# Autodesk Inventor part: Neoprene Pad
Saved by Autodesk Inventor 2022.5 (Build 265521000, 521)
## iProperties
Created: 2025-02
Part Number: Neoprene Pad
Material: Generic
Document SubType Name: Modeling
Designer: AdminForWorker
Density: 1 g/cm^3
Appearance: Default
Title: Neoprene Pad
Author: AdminForWorker
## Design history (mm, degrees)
feature "Neoprene Pad"
body "Solid1"
